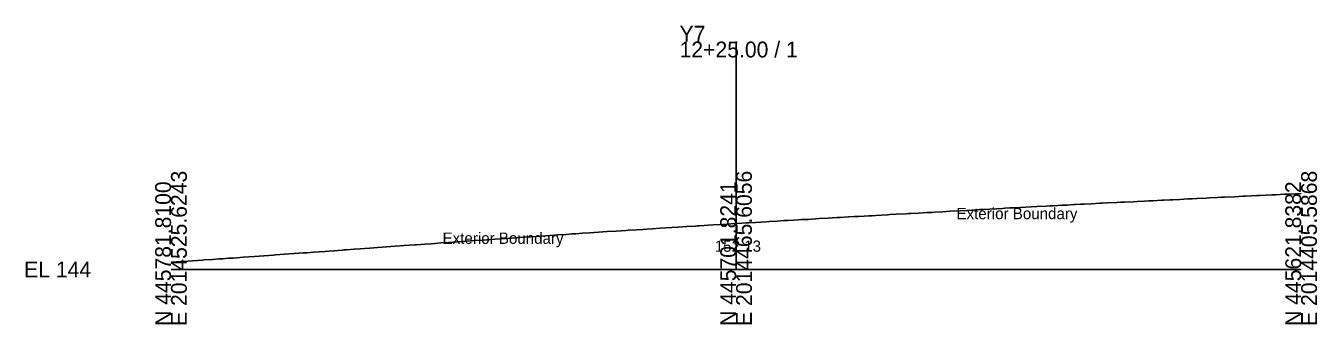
# Model space of a CAD drawing. Extents: x -26 to 203, y -10 to 7527.
# Drawn here: x -25.7 to 202.8, y 4490.3 to 4543.2 of the extents above; entities that cross this region are included whole.
import ezdxf

# ---------------------------------------------------------------- set-up
doc = ezdxf.new("R2010")
doc.units = 0
for name, color, linetype in [('Exist Cross Section Cell', 7, 'Continuous'), ('Exist XS Center Line Elevation Label', 7, 'Continuous'), ('Exist XS Ground Line', 7, 'Continuous'), ('Scratch_Level_0', 7, 'Continuous')]:
    doc.layers.add(name, color=color, linetype=linetype)

msp = doc.modelspace()

# ---------------------------------------------------------------- linework, layer by layer
at = {"layer": 'Exist Cross Section Cell'}
for p, q in [((100, 4500), (100, 4540.36)), ((0, 4500), (100, 4500)), ((100, 4500), (200, 4500))]:
    msp.add_line(p, q, dxfattribs=at)
at = {"layer": 'Exist XS Ground Line'}
msp.add_lwpolyline([(0, 4501.27), (1.77, 4501.4), (2.19, 4501.43), (3.78, 4501.54), (5.56, 4501.66), (5.88, 4501.68), (7.37, 4501.78), (8.45, 4501.86), (9.17, 4501.91), (10.17, 4501.98), (10.98, 4502.03), (11.58, 4502.08), (12.78, 4502.18), (14.71, 4502.3), (15.63, 4502.37), (18.12, 4502.55), (18.52, 4502.58), (20.94, 4502.76), (22.56, 4502.87), (23.41, 4502.92), (24.05, 4502.97), (25.22, 4503.07), (27.2, 4503.2), (28.82, 4503.33), (30.33, 4503.43), (30.63, 4503.45), (31.06, 4503.48), (32.43, 4503.59), (33.46, 4503.66), (34.22, 4503.72), (35.21, 4503.79), (36.59, 4503.89), (39.66, 4504.11), (41.28, 4504.23), (43.09, 4504.35), (43.46, 4504.38), (44.91, 4504.49), (45.97, 4504.56), (46.73, 4504.62), (47.74, 4504.69), (49.1, 4504.78), (52.19, 4505.01), (53.79, 4505.12), (55.33, 4505.21), (55.89, 4505.25), (57.38, 4505.37), (58.46, 4505.44), (59.2, 4505.49), (60.22, 4505.56), (61.59, 4505.65), (64.7, 4505.85), (66.3, 4505.97), (67.83, 4506.07), (68.41, 4506.11), (69.89, 4506.22), (70.97, 4506.29), (71.62, 4506.33), (72.74, 4506.41), (74.1, 4506.5), (77.2, 4506.71), (78.8, 4506.81), (80.57, 4506.93), (80.89, 4506.95), (82.39, 4507.05), (83.48, 4507.11), (84.22, 4507.14), (85.21, 4507.22), (86.59, 4507.31), (89.67, 4507.5), (91.3, 4507.6), (92.83, 4507.7), (93.13, 4507.71), (93.54, 4507.74), (95.94, 4507.89), (97.58, 4507.99), (98.42, 4508.05), (99.07, 4508.08), (100.23, 4508.14), (101.83, 4508.25), (102.21, 4508.27), (103.42, 4508.35), (105.31, 4508.46), (105.91, 4508.5), (107.36, 4508.58), (108.45, 4508.65), (109.17, 4508.68), (110.15, 4508.75), (110.98, 4508.8), (111.59, 4508.83), (112.77, 4508.88), (114.72, 4509.01), (116.3, 4509.08), (117.84, 4509.18), (118.44, 4509.22), (119.89, 4509.3), (120.97, 4509.36), (121.66, 4509.39), (122.65, 4509.45), (123.47, 4509.5), (124.1, 4509.53), (124.72, 4509.56), (126.79, 4509.69), (127.22, 4509.71), (128.32, 4509.77), (130.14, 4509.87), (130.54, 4509.9), (130.91, 4509.92), (132.37, 4510), (133.73, 4510.07), (134.68, 4510.12), (135.19, 4510.15), (136.58, 4510.23), (137.81, 4510.3), (139.67, 4510.41), (140.82, 4510.47), (142.62, 4510.57), (143.11, 4510.6), (143.63, 4510.63), (146.16, 4510.76), (147.18, 4510.82), (147.56, 4510.84), (148.44, 4510.89), (149.09, 4510.92), (150.33, 4510.99), (152.23, 4511.09), (153.24, 4511.14), (154.99, 4511.24), (155.57, 4511.27), (156.18, 4511.3), (157.73, 4511.38), (158.57, 4511.42), (159.71, 4511.48), (160.05, 4511.5), (160.93, 4511.54), (161.59, 4511.57), (162.86, 4511.63), (164.35, 4511.72), (164.77, 4511.74), (165.7, 4511.78), (167.39, 4511.86), (168.06, 4511.9), (168.77, 4511.93), (170.27, 4512.01), (171, 4512.04), (172.3, 4512.11), (173.03, 4512.14), (173.76, 4512.18), (175.37, 4512.26), (175.71, 4512.28), (176.83, 4512.34), (177.27, 4512.36), (178.54, 4512.42), (179.94, 4512.49), (180.73, 4512.53), (181.58, 4512.57), (183.22, 4512.65), (183.73, 4512.67), (185.21, 4512.74), (185.93, 4512.78), (186.45, 4512.81), (188.23, 4512.89), (189.68, 4512.96), (190.15, 4512.99), (192.14, 4513.08), (192.83, 4513.11), (193.83, 4513.16), (194.84, 4513.21), (195.48, 4513.24), (197.12, 4513.31), (197.47, 4513.33), (198.01, 4513.36), (200, 4513.45)], dxfattribs=at)

# ---------------------------------------------------------------- texts
at = {"layer": 'Exist Cross Section Cell'}
for s, p in [('Y7', (90, 4540.36)), ('12+25.00 / 1', (90, 4537.56)), ('EL 144', (-26, 4498.6))]:
    msp.add_text(s, height=2.8, dxfattribs=at).set_placement(p)
for s, p in [('E 2014525.6243', (2.8, 4490)), ('E 2014465.6056', (102.8, 4490)), ('E 2014405.5868', (202.8, 4490)), ('N 445781.8100', (0, 4490)), ('N 445701.8241', (100, 4490)), ('N 445621.8382', (200, 4490))]:
    msp.add_text(s, height=2.8, rotation=90, dxfattribs=at).set_placement(p)
at = {"layer": 'Exist XS Center Line Elevation Label'}
msp.add_text('152.13', height=2, dxfattribs=at).set_placement((96.23, 4503.13))
at = {"layer": 'Scratch_Level_0'}
for p in [(139.01, 4508.91), (48.06, 4504.54)]:
    msp.add_text('Exterior Boundary', height=2, dxfattribs=at).set_placement(p)

doc.saveas('drawing.dxf')
